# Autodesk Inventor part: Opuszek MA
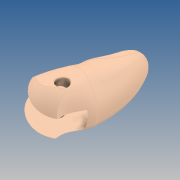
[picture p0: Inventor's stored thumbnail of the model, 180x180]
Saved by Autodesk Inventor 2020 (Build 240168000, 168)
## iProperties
Created: 2019-10
Part Number: Opuszek MA
Material: GFRP
Document SubType Name: Modeling
Designer: yello
Density: 1.75 g/cm^3
Appearance: Default
Author: yello
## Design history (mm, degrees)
feature "Opuszek MA"
sketch "Sketch1"
  geometry: C1 r 2 at (0, 0); 1 further point
  constraints: 1 centre point
  dimensions: "d0" = 4 diameter of C1
extrude "Extrusion1" cut sketch "Sketch1" stored distance "d1" = 100; taper "d2" = 0 deg
body "Solid1"
